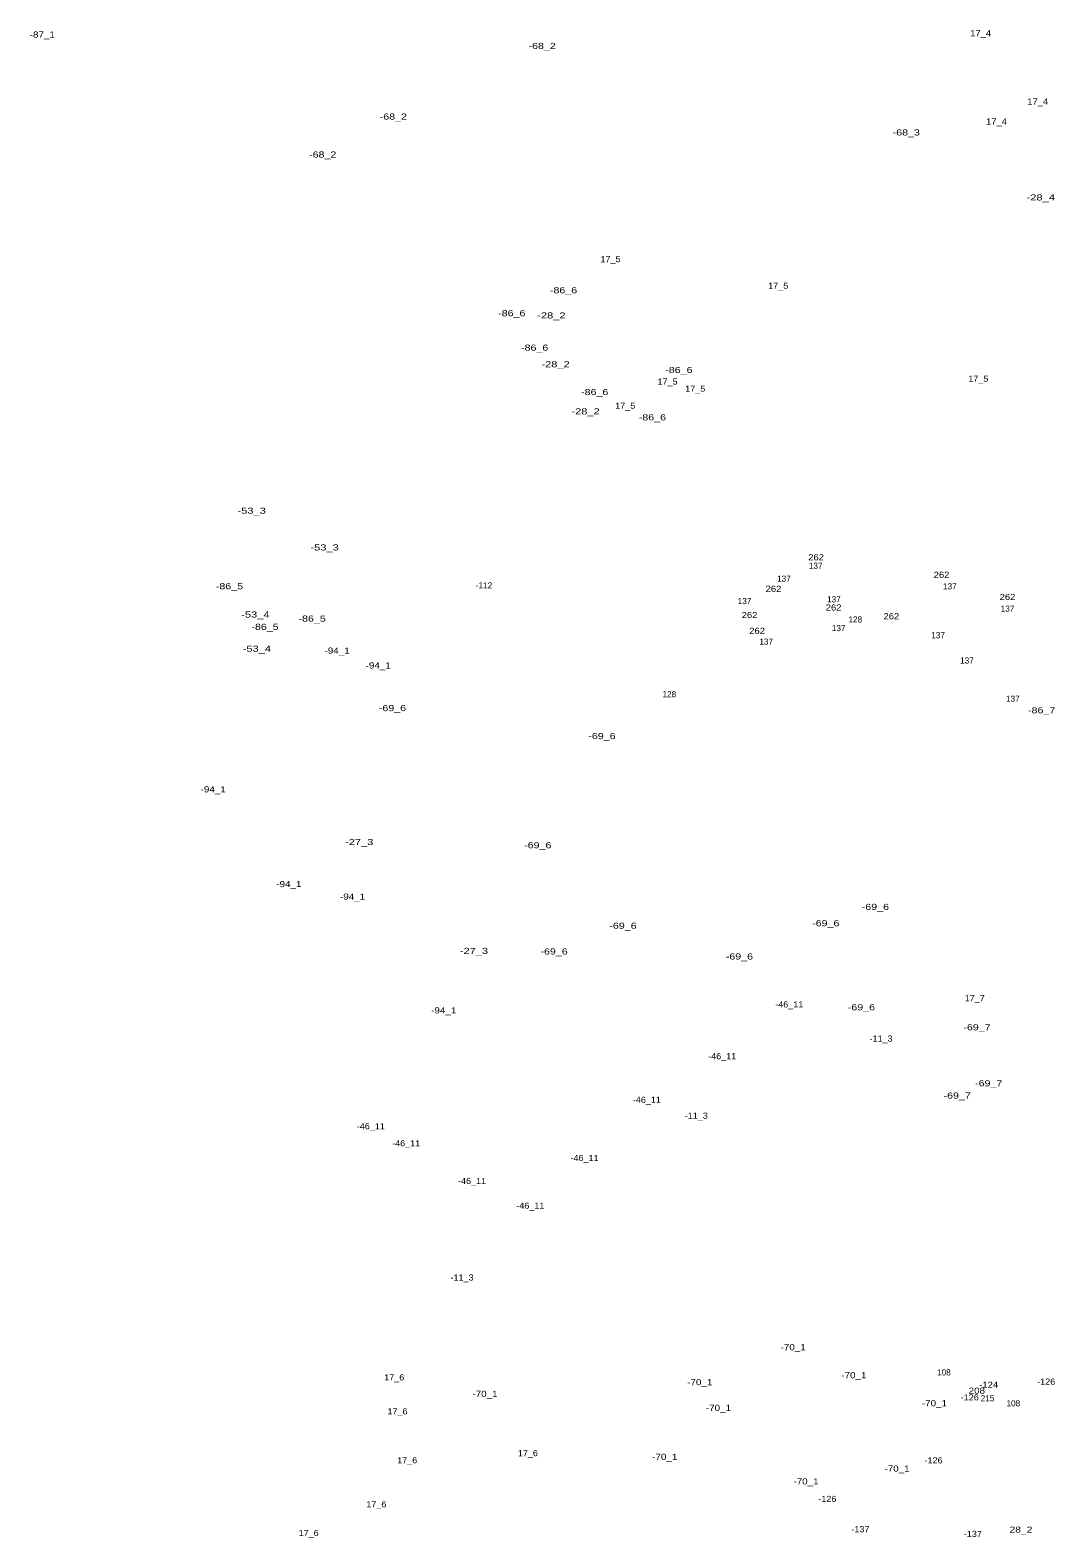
# Model space of a CAD drawing. Extents: x -662996 to -659766, y -998554 to -993949.
# Drawn here: x -662169 to -661500, y -997265 to -996281 of the extents above; entities that cross this region are included whole.
import ezdxf
from ezdxf.enums import TextEntityAlignment as Align

# ---------------------------------------------------------------- set-up
doc = ezdxf.new("R2010")
doc.units = 0
doc.header["$LTSCALE"] = 1.6
doc.layers.add('24', color=7, linetype='Continuous')

msp = doc.modelspace()

# ---------------------------------------------------------------- texts
at = {"layer": '24'}
for s, width, p in [('-87_1', 1.2, (-662160.84, -996285.41)), ('-68_2', 1.3, (-661834.68, -996292.85)), ('17_4', 1.15, (-661548.559, -996284.54)), ('17_4', 1.15, (-661511.309, -996329.11)), ('-68_2', 1.3, (-661931.79, -996338.95)), ('17_4', 1.15, (-661538.189, -996342.17)), ('-68_3', 1.3, (-661597.08, -996349.29)), ('-68_2', 1.3, (-661977.87, -996363.71)), ('-28_4', 1.35, (-661509.32, -996391.72)), ('17_5', 1.1, (-661790.079, -996432.02)), ('17_5', 1.1, (-661680.64, -996449.3)), ('-86_6', 1.3, (-661820.73, -996452.33)), ('-86_6', 1.3, (-661854.52, -996467.31)), ('-28_2', 1.35, (-661828.63, -996468.75)), ('-86_6', 1.3, (-661839.55, -996489.78)), ('-28_2', 1.35, (-661825.939, -996500.63)), ('-86_6', 1.3, (-661745.46, -996504.37)), ('17_5', 1.1, (-661550.069, -996510)), ('-86_6', 1.3, (-661800.38, -996518.78)), ('17_5', 1.1, (-661752.829, -996511.92)), ('17_5', 1.1, (-661734.78, -996516.53)), ('17_5', 1.1, (-661780.48, -996527.67)), ('-28_2', 1.35, (-661806.35, -996531.36)), ('-86_6', 1.3, (-661762.74, -996535.29)), ('-53_3', 1.35, (-662024.24, -996596.2)), ('-53_3', 1.35, (-661976.64, -996620.2)), ('262', 1.15, (-661655.94, -996626.62)), ('262', 1.15, (-661574.06, -996638.05)), ('-86_5', 1.3, (-662038.74, -996645.52)), ('262', 1.15, (-661683.73, -996647.2)), ('262', 1.15, (-661531.03, -996652.53)), ('-53_4', 1.35, (-662021.79, -996664)), ('-86_5', 1.3, (-661984.79, -996666.65)), ('262', 1.15, (-661699.35, -996664.34)), ('262', 1.15, (-661644.51, -996659.39)), ('262', 1.15, (-661606.81, -996665.1)), ('-86_5', 1.3, (-662015.51, -996672.03)), ('262', 1.15, (-661694.4, -996674.62)), ('-53_4', 1.35, (-662020.84, -996686.29)), ('-94_1', 1.2, (-661968.48, -996687.54)), ('-94_1', 1.2, (-661941.66, -996697.26)), ('-69_6', 1.3, (-661932.36, -996725.06)), ('-86_7', 1.3, (-661508.731, -996726.51)), ('-69_6', 1.3, (-661795.65, -996743.35)), ('-94_1', 1.2, (-662049.33, -996778.13)), ('-27_3', 1.35, (-661954.06, -996812.5)), ('-69_6', 1.3, (-661837.54, -996814.59)), ('-94_1', 1.2, (-661999.96, -996839.96)), ('-94_1', 1.2, (-661958.38, -996848.12)), ('-69_6', 1.3, (-661617.24, -996854.83)), ('-69_6', 1.3, (-661781.939, -996867.16)), ('-69_6', 1.3, (-661649.61, -996865.5)), ('-27_3', 1.35, (-661879.17, -996883.57)), ('-69_6', 1.3, (-661826.87, -996883.92)), ('-69_6', 1.3, (-661705.97, -996887.21)), ('-94_1', 1.2, (-661898.91, -996922.39)), ('-46_11', 1.1, (-661673.42, -996918.5)), ('-69_6', 1.3, (-661626.38, -996920.36)), ('17_7', 1.1, (-661552.44, -996914.42)), ('-69_7', 1.3, (-661550.929, -996933.42)), ('-11_3', 1.1, (-661613.52, -996940.78)), ('-46_11', 1.1, (-661717.2, -996952.3)), ('-69_7', 1.3, (-661543.309, -996969.99)), ('-46_11', 1.1, (-661766.35, -996980.73)), ('-69_7', 1.3, (-661563.87, -996977.99)), ('-11_3', 1.1, (-661734.1, -996991.11)), ('-46_11', 1.1, (-661946.46, -996998.02)), ('-46_11', 1.1, (-661923.41, -997009.16)), ('-46_11', 1.1, (-661807.06, -997018.76)), ('-46_11', 1.1, (-661880.41, -997033.74)), ('-46_11', 1.1, (-661842.39, -997049.88)), ('-11_3', 1.1, (-661886.939, -997096.75)), ('-70_1', 1.2, (-661670.89, -997142.24)), ('17_6', 1.1, (-661931.191, -997161.95)), ('-70_1', 1.2, (-661731.821, -997165.09)), ('-70_1', 1.2, (-661631.28, -997160.52)), ('-124', 1.15, (-661543.31, -997166.78)), ('-126', 1.1, (-661505.77, -997164.72)), ('-70_1', 1.2, (-661871.961, -997172.71)), ('-70_1', 1.2, (-661578.731, -997178.81)), ('-126', 1.1, (-661555.65, -997174.99)), ('208', 1.2, (-661551.049, -997170.6)), ('17_6', 1.1, (-661929.071, -997184.12)), ('-70_1', 1.2, (-661719.63, -997181.86)), ('17_6', 1.1, (-661922.74, -997216.05)), ('17_6', 1.1, (-661844.01, -997211.44)), ('-70_1', 1.2, (-661754.671, -997213.86)), ('-126', 1.1, (-661579.27, -997216.13)), ('-70_1', 1.2, (-661603.101, -997221.47)), ('-70_1', 1.2, (-661662.51, -997229.86)), ('17_6', 1.1, (-661942.89, -997244.81)), ('-126', 1.1, (-661648.57, -997241.29)), ('17_6', 1.1, (-661987.051, -997263.55)), ('-137', 1.1, (-661627.02, -997261.06)), ('-137', 1.1, (-661553.66, -997264.13)), ('28_2', 1.25, (-661522.26, -997261.36))]:
    msp.add_text(s, height=4, dxfattribs=dict(at, width=width)).set_placement(p, align=Align.CENTER)
for s, p in [('137', (-661656.191, -996632.13)), ('-112', (-661872.66, -996645)), ('137', (-661676.931, -996640.58)), ('137', (-661568.64, -996645.57)), ('137', (-661702.66, -996655.18)), ('137', (-661644.291, -996654.02)), ('128', (-661630.35, -996667.19)), ('137', (-661531, -996660.17)), ('137', (-661641.211, -996672.85)), ('137', (-661576.321, -996677.46)), ('137', (-661688.451, -996681.68)), ('137', (-661557.5, -996693.98)), ('128', (-661751.699, -996715.98)), ('137', (-661527.551, -996718.95)), ('108', (-661572.54, -997158.7)), ('215', (-661544.09, -997175.59)), ('108', (-661527.23, -997178.87))]:
    msp.add_text(s, height=4, dxfattribs=at).set_placement(p, align=Align.CENTER)

doc.saveas('drawing.dxf')
